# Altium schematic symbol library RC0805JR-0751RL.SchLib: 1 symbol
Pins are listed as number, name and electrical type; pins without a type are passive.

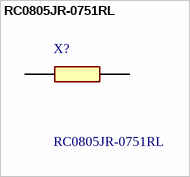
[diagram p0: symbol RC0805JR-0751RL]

## RC0805JR-0751RL
designator X?
Thick Film Resistors - SMD 51 Ohms 125 mW 0805  5%; Manufacturer_Name: YAGEO; Geometry.Height: 0.6mm
footprint RESC2012X60N
pins: 1, 2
